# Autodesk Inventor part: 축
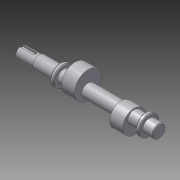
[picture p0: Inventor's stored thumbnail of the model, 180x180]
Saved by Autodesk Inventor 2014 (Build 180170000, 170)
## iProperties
Created: 2014-12
Part Number: 축
Material: 알루미늄 6061
Document SubType Name: Modeling
Designer: Owner
Density: 2.71 g/cm^3
Appearance: 알루미늄 - 평지
Mass: 170.354 g
Surface Area: 153.402 cm^2
Volume: 62.8614 cm^3
Author: Owner
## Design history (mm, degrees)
sketch "스케치1"
  geometry: L1 (-90, 0)-(90, 0); L2 (-90, 0)-(-90, 7.5); L3 (-90, 7.5)-(-66, 7.5); L4 (-66, 7.5)-(-66, 8.5); L5 (-66, 8.5)-(-39, 8.5); L6 (-39, 8.5)-(-39, 13); L7 (-39, 13)-(-34, 13); L8 (-34, 13)-(-34, 8.5); L9 (-34, 8.5)-(72, 8.5); L10 (72, 13)-(72, 8.5); L11 (72, 13)-(77, 13); L12 (77, 13)-(77, 8.5); L13 (77, 8.5)-(90, 8.5); L14 (90, 8.5)-(90, 0); 2 further points
  constraints: 28 end point, 7 parallel, 6 perpendicular, 2 horizontal alignment, 1 coincident, 1 horizontal, 1 midpoint
  dimensions: "d0" = 180 distance of L1.start L1.end; "d1" = 15 diameter of L3 L1; "d2" = 17 diameter of L5 L1; "d3" = 26 diameter of L7 L1; "d4" = 5 distance between parallel lines of L8 L6; "d5" = 5 distance between parallel lines of L12 L10; "d6" = 26 diameter of L11 L1; "d7" = 24 distance between parallel lines of L4 L2; "d8" = 27 distance between parallel lines of L6 L4; "d9" = 13 distance between parallel lines of L14 L12
revolve "회전1" sketch "스케치1" stored, may be unused: angle "d10" = 90 deg
node "작업 평면1"
sketch "스케치2"
  geometry: C1 r 17.5 at (-6, 0); 1 further point
  constraints: 1 centre point, 1 horizontal alignment
  dimensions: "d12" = 35 diameter of C1; "d13" = 6 distance of point (0, 0) C1.centre
extrude "돌출1" join sketch "스케치2" distance "d14" = 17; taper "d15" = 0 deg
node "작업 평면2"
sketch "스케치3"
  geometry: C1 r 15 at (-5, 0); 1 further point
  constraints: 1 centre point, 1 horizontal alignment
  dimensions: "d17" = 30 diameter of C1; "d18" = 5 distance of C1.centre point (0, 0)
extrude "돌출2" join sketch "스케치3" distance "d19" = 17; taper "d20" = 0 deg
node "작업 평면3"
sketch "스케치4"
  geometry: L1 (-12, -7.5)-(-12, 7.5) reference; L2 (-12, 7.5)-(12, 7.5) reference; L3 (-12, -7.5)-(12, -7.5) reference; L4 (-12, 2.5)-(5.5, 2.5); L5 (5.5, -2.5)-(-12, -2.5); L6 (-12, -2.5)-(-12, 2.5); A1 r 2.5 centre (5.5, 0) between (5.5, -2.5) and (5.5, 2.5); 3 further points
  constraints: 6 end point, 2 midpoint, 2 parallel, 2 point on circle, 1 centre point, 1 coincident, 1 horizontal, 1 horizontal alignment, 1 point on line
  dimensions: "d21" = 5 distance between parallel lines of L5 L4; "d23" = 2.5 radius of A1; "d24" = 17.5 distance of L4.start L4.end
extrude "돌출3" cut sketch "스케치4" distance "d25" = 3; taper "d26" = 0 deg
chamfer "모따기1" distance "d27" = 1; stored, may be unused: second distance "d28" = 2, angle "d29" = 45 deg
chamfer "모따기2" distance "d30" = 1; stored, may be unused: second distance "d31" = 2, angle "d32" = 45 deg
chamfer "모따기3" distance "d33" = 1; stored, may be unused: second distance "d34" = 2, angle "d35" = 45 deg
chamfer "모따기4" distance "d36" = 1; stored, may be unused: second distance "d37" = 2, angle "d38" = 45 deg
node "솔리드1"
other parameters: "d11" = 14.5, "d16" = 14.5
